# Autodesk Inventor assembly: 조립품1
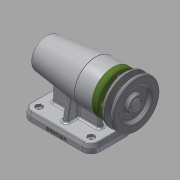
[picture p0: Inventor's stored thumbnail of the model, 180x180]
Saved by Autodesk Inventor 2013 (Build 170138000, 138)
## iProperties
Created: 2017-01
Part Number: 조립품1
Document SubType Name: Assembly
Designer: Administrator
Author: Administrator
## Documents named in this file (12)
- C:\Users\Administrator\Desktop\오정훈\조립품1.iam
- C:\Users\Administrator\Desktop\오정훈\본체.ipt
- C:\Users\Administrator\Desktop\오정훈\470107V1008\V벨트풀리.ipt
- C:\Users\Administrator\Desktop\오정훈\470107V1008\멈춤나사 M3x8.ipt
- C:\Users\Administrator\Desktop\오정훈\470107V1008\베어링 6004.ipt
- C:\Users\Administrator\Desktop\오정훈\470107V1008\베어링 51202.ipt
- C:\Users\Administrator\Desktop\오정훈\470107V1008\볼트 M4 x 12.ipt
- C:\Users\Administrator\Desktop\오정훈\470107V1008\어댑터슬리브.ipt
- C:\Users\Administrator\Desktop\오정훈\470107V1008\오일 실.ipt
- C:\Users\Administrator\Desktop\오정훈\470107V1008\축.ipt
- C:\Users\Administrator\Desktop\오정훈\470107V1008\커버.ipt
- C:\Users\Administrator\Desktop\오정훈\470107V1008\키 5 x 5 x 16.ipt
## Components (6 placed, 2 different names)
1. V벨트풀리:1
2. ISO 4762 M4 x 12:1
3. ISO 4762 M4 x 12:2
4. ISO 4762 M4 x 12:3
5. ISO 4762 M4 x 12:4
6. ISO 4762 M4 x 12:5
